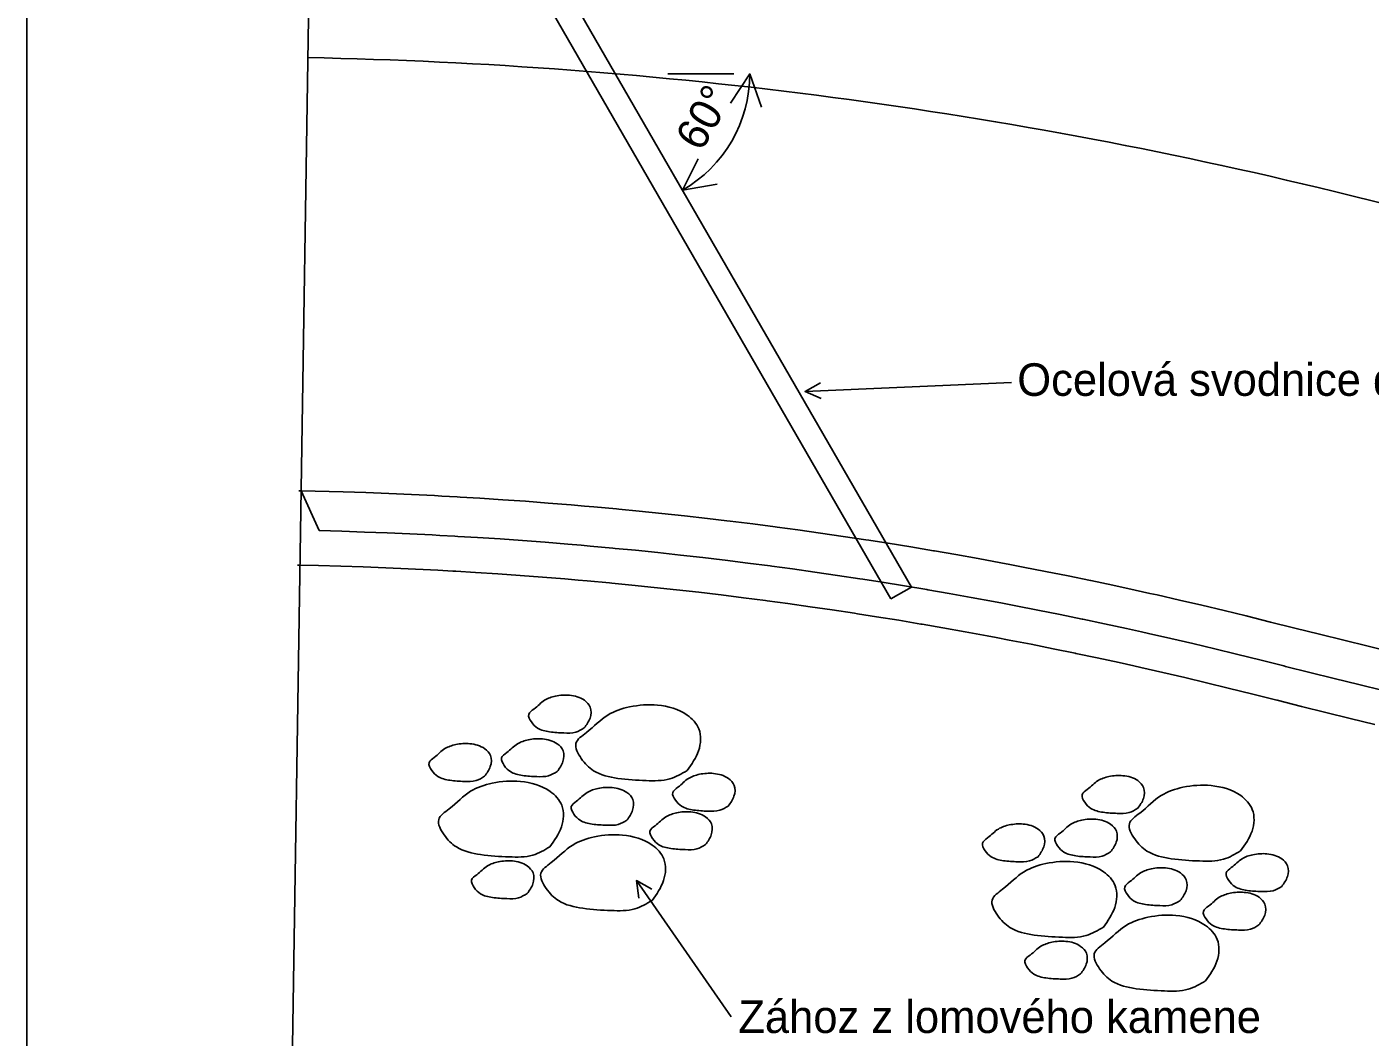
# Model space of a CAD drawing. Extents: x -577013.5 to -576971.5, y -1164310.3 to -1164280.6.
# Drawn here: x -577013.45 to -577004.93, y -1164296.24 to -1164289.83 of the extents above; entities that cross this region are included whole.
import ezdxf

# ---------------------------------------------------------------- set-up
doc = ezdxf.new("R2010")
doc.units = 0
for name, color, linetype in [('5', 7, 'Continuous'), ('Rámy', 7, 'Continuous'), ('V_N1_detaily', 7, 'Continuous'), ('Vrstva 1', 7, 'Continuous')]:
    doc.layers.add(name, color=color, linetype=linetype)

msp = doc.modelspace()

# ---------------------------------------------------------------- linework, layer by layer
for p, q in [((-577011.5826, -1164284.2581), (-577011.8184, -1164299.5379)), ((-577011.5089, -1164287.0275), (-577007.84, -1164293.3847)), ((-577007.9699, -1164293.4597), (-577011.6388, -1164287.1025)), ((-577009.3869, -1164290.1276), (-577008.9662, -1164290.128)), ((-577009.2943, -1164290.8648), (-577009.3432, -1164290.7801)), ((-577011.714, -1164292.7743), (-577011.7277, -1164292.7741)), ((-577011.4471, -1164292.7811), (-577011.714, -1164292.7737)), ((-577011.5982, -1164293.027), (-577011.714, -1164292.7743)), ((-577011.3022, -1164292.7859), (-577011.4471, -1164292.7811)), ((-577011.1574, -1164292.7914), (-577011.3022, -1164292.7859)), ((-577011.0127, -1164292.7977), (-577011.1574, -1164292.7914)), ((-577010.8679, -1164292.8048), (-577011.0127, -1164292.7977)), ((-577010.8202, -1164292.8073), (-577010.8679, -1164292.8048)), ((-577010.7232, -1164292.8126), (-577010.8202, -1164292.8073)), ((-577010.7043, -1164292.8137), (-577010.7232, -1164292.8126)), ((-577010.5786, -1164292.8212), (-577010.7043, -1164292.8137)), ((-577010.4339, -1164292.8306), (-577010.5786, -1164292.8212)), ((-577010.2894, -1164292.8408), (-577010.4339, -1164292.8306)), ((-577010.1449, -1164292.8517), (-577010.2894, -1164292.8408)), ((-577010.0004, -1164292.8634), (-577010.1449, -1164292.8517)), ((-577009.9141, -1164292.8707), (-577010.0004, -1164292.8634)), ((-577009.8561, -1164292.8758), (-577009.9141, -1164292.8707)), ((-577009.7117, -1164292.889), (-577009.8561, -1164292.8758)), ((-577009.6967, -1164292.8905), (-577009.7117, -1164292.889)), ((-577009.5675, -1164292.903), (-577009.6967, -1164292.8905)), ((-577009.4234, -1164292.9178), (-577009.5675, -1164292.903)), ((-577009.2793, -1164292.9333), (-577009.4234, -1164292.9178)), ((-577009.1353, -1164292.9496), (-577009.2793, -1164292.9333)), ((-577009.0106, -1164292.9643), (-577009.1353, -1164292.9496)), ((-577008.9914, -1164292.9667), (-577009.0106, -1164292.9643)), ((-577008.8476, -1164292.9845), (-577008.9914, -1164292.9667)), ((-577008.7038, -1164293.0031), (-577008.8476, -1164292.9845)), ((-577008.6927, -1164293.0045), (-577008.7038, -1164293.0031)), ((-577008.5602, -1164293.0224), (-577008.6927, -1164293.0045)), ((-577011.4546, -1164293.031), (-577011.5982, -1164293.027)), ((-577011.3111, -1164293.0357), (-577011.4546, -1164293.031)), ((-577011.1676, -1164293.0412), (-577011.3111, -1164293.0357)), ((-577011.0242, -1164293.0474), (-577011.1676, -1164293.0412)), ((-577010.8808, -1164293.0544), (-577011.0242, -1164293.0474)), ((-577010.8335, -1164293.0569), (-577010.8808, -1164293.0544)), ((-577010.7374, -1164293.0622), (-577010.8335, -1164293.0569)), ((-577010.7187, -1164293.0633), (-577010.7374, -1164293.0622)), ((-577010.5941, -1164293.0707), (-577010.7187, -1164293.0633)), ((-577010.4508, -1164293.08), (-577010.5941, -1164293.0707)), ((-577010.3076, -1164293.0901), (-577010.4508, -1164293.08)), ((-577010.1644, -1164293.1009), (-577010.3076, -1164293.0901)), ((-577008.4167, -1164293.0425), (-577008.5602, -1164293.0224)), ((-577008.2733, -1164293.0634), (-577008.4167, -1164293.0425)), ((-577008.13, -1164293.085), (-577008.2733, -1164293.0634)), ((-577008.1108, -1164293.088), (-577008.13, -1164293.085)), ((-577007.9868, -1164293.1074), (-577008.1108, -1164293.088)), ((-577010.0213, -1164293.1125), (-577010.1644, -1164293.1009)), ((-577009.9357, -1164293.1198), (-577010.0213, -1164293.1125)), ((-577009.8782, -1164293.1248), (-577009.9357, -1164293.1198)), ((-577009.7352, -1164293.1379), (-577009.8782, -1164293.1248)), ((-577009.7203, -1164293.1393), (-577009.7352, -1164293.1379)), ((-577009.5923, -1164293.1518), (-577009.7203, -1164293.1393)), ((-577009.4495, -1164293.1664), (-577009.5923, -1164293.1518)), ((-577009.3067, -1164293.1818), (-577009.4495, -1164293.1664)), ((-577009.164, -1164293.1979), (-577009.3067, -1164293.1818)), ((-577007.8438, -1164293.1306), (-577007.9868, -1164293.1074)), ((-577007.7009, -1164293.1545), (-577007.8438, -1164293.1306)), ((-577007.6935, -1164293.1558), (-577007.7009, -1164293.1545)), ((-577007.5581, -1164293.1792), (-577007.6935, -1164293.1558)), ((-577007.4154, -1164293.2046), (-577007.5581, -1164293.1792)), ((-577011.7236, -1164293.2461), (-577011.7373, -1164293.2458)), ((-577011.6037, -1164293.2488), (-577011.7236, -1164293.2461)), ((-577011.4613, -1164293.2527), (-577011.6037, -1164293.2488)), ((-577011.319, -1164293.2574), (-577011.4613, -1164293.2527)), ((-577011.1767, -1164293.2629), (-577011.319, -1164293.2574)), ((-577011.0344, -1164293.2691), (-577011.1767, -1164293.2629)), ((-577010.8922, -1164293.276), (-577011.0344, -1164293.2691)), ((-577009.0406, -1164293.2125), (-577009.164, -1164293.1979)), ((-577009.0214, -1164293.2148), (-577009.0406, -1164293.2125)), ((-577008.879, -1164293.2325), (-577009.0214, -1164293.2148)), ((-577008.7366, -1164293.2509), (-577008.879, -1164293.2325)), ((-577008.7255, -1164293.2524), (-577008.7366, -1164293.2509)), ((-577008.5943, -1164293.2701), (-577008.7255, -1164293.2524)), ((-577007.2729, -1164293.2308), (-577007.4154, -1164293.2046)), ((-577007.2156, -1164293.2416), (-577007.2729, -1164293.2308)), ((-577007.1305, -1164293.2578), (-577007.2156, -1164293.2416)), ((-577006.9882, -1164293.2855), (-577007.1305, -1164293.2578)), ((-577010.8453, -1164293.2785), (-577010.8922, -1164293.276)), ((-577010.75, -1164293.2837), (-577010.8453, -1164293.2785)), ((-577010.7314, -1164293.2848), (-577010.75, -1164293.2837)), ((-577010.6078, -1164293.2922), (-577010.7314, -1164293.2848)), ((-577010.4657, -1164293.3014), (-577010.6078, -1164293.2922)), ((-577010.3237, -1164293.3114), (-577010.4657, -1164293.3014)), ((-577010.1817, -1164293.3221), (-577010.3237, -1164293.3114)), ((-577010.0397, -1164293.3336), (-577010.1817, -1164293.3221)), ((-577009.9549, -1164293.3408), (-577010.0397, -1164293.3336)), ((-577009.8979, -1164293.3458), (-577009.9549, -1164293.3408)), ((-577009.7561, -1164293.3588), (-577009.8979, -1164293.3458)), ((-577008.4521, -1164293.29), (-577008.5943, -1164293.2701)), ((-577008.31, -1164293.3107), (-577008.4521, -1164293.29)), ((-577008.168, -1164293.3321), (-577008.31, -1164293.3107)), ((-577008.149, -1164293.3351), (-577008.168, -1164293.3321)), ((-577008.0261, -1164293.3543), (-577008.149, -1164293.3351)), ((-577007.8844, -1164293.3773), (-577008.0261, -1164293.3543)), ((-577006.8461, -1164293.314), (-577006.9882, -1164293.2855)), ((-577006.7042, -1164293.3432), (-577006.8461, -1164293.314)), ((-577006.7007, -1164293.3439), (-577006.7042, -1164293.3432)), ((-577006.5624, -1164293.3732), (-577006.7007, -1164293.3439)), ((-577009.7413, -1164293.3602), (-577009.7561, -1164293.3588)), ((-577009.6143, -1164293.3726), (-577009.7413, -1164293.3602)), ((-577009.4726, -1164293.3871), (-577009.6143, -1164293.3726)), ((-577009.3311, -1164293.4023), (-577009.4726, -1164293.3871)), ((-577009.1896, -1164293.4183), (-577009.3311, -1164293.4023)), ((-577009.0671, -1164293.4328), (-577009.1896, -1164293.4183)), ((-577009.0481, -1164293.4351), (-577009.0671, -1164293.4328)), ((-577008.9068, -1164293.4526), (-577009.0481, -1164293.4351)), ((-577007.84, -1164293.3847), (-577007.9699, -1164293.4597)), ((-577007.7428, -1164293.401), (-577007.8844, -1164293.3773)), ((-577007.7355, -1164293.4022), (-577007.7428, -1164293.401)), ((-577007.6013, -1164293.4254), (-577007.7355, -1164293.4022)), ((-577007.4599, -1164293.4506), (-577007.6013, -1164293.4254)), ((-577006.4208, -1164293.4039), (-577006.5624, -1164293.3732)), ((-577006.326, -1164293.4249), (-577006.4208, -1164293.4039)), ((-577006.2794, -1164293.4354), (-577006.326, -1164293.4249)), ((-577006.1381, -1164293.4676), (-577006.2794, -1164293.4354)), ((-577008.7656, -1164293.4709), (-577008.9068, -1164293.4526)), ((-577008.7546, -1164293.4723), (-577008.7656, -1164293.4709)), ((-577008.6245, -1164293.4899), (-577008.7546, -1164293.4723)), ((-577008.4834, -1164293.5096), (-577008.6245, -1164293.4899)), ((-577008.3425, -1164293.5302), (-577008.4834, -1164293.5096)), ((-577007.3187, -1164293.4766), (-577007.4599, -1164293.4506)), ((-577007.262, -1164293.4872), (-577007.3187, -1164293.4766)), ((-577007.1776, -1164293.5033), (-577007.262, -1164293.4872)), ((-577007.0367, -1164293.5307), (-577007.1776, -1164293.5033)), ((-577005.997, -1164293.5006), (-577006.1381, -1164293.4676)), ((-577005.856, -1164293.5343), (-577005.997, -1164293.5006)), ((-577008.2017, -1164293.5514), (-577008.3425, -1164293.5302)), ((-577008.1828, -1164293.5543), (-577008.2017, -1164293.5514)), ((-577008.061, -1164293.5734), (-577008.1828, -1164293.5543)), ((-577007.9204, -1164293.5962), (-577008.061, -1164293.5734)), ((-577007.78, -1164293.6197), (-577007.9204, -1164293.5962)), ((-577006.8959, -1164293.559), (-577007.0367, -1164293.5307)), ((-577006.7553, -1164293.5879), (-577006.8959, -1164293.559)), ((-577006.7518, -1164293.5886), (-577006.7553, -1164293.5879)), ((-577006.6148, -1164293.6176), (-577006.7518, -1164293.5886)), ((-577005.7156, -1164293.5687), (-577005.856, -1164293.5343)), ((-577005.5604, -1164293.6072), (-577005.7156, -1164293.5687)), ((-577005.4151, -1164293.6432), (-577005.5604, -1164293.6072)), ((-577007.7728, -1164293.6209), (-577007.78, -1164293.6197)), ((-577007.6397, -1164293.6439), (-577007.7728, -1164293.6209)), ((-577007.4995, -1164293.6689), (-577007.6397, -1164293.6439)), ((-577007.3594, -1164293.6947), (-577007.4995, -1164293.6689)), ((-577007.3031, -1164293.7052), (-577007.3594, -1164293.6947)), ((-577006.4745, -1164293.6481), (-577006.6148, -1164293.6176)), ((-577006.3805, -1164293.6689), (-577006.4745, -1164293.6481)), ((-577006.3343, -1164293.6793), (-577006.3805, -1164293.6689)), ((-577006.1943, -1164293.7112), (-577006.3343, -1164293.6793)), ((-577005.4055, -1164293.6456), (-577005.4151, -1164293.6432)), ((-577005.2507, -1164293.684), (-577005.4055, -1164293.6456)), ((-577005.0958, -1164293.7223), (-577005.2507, -1164293.684)), ((-577007.2195, -1164293.7212), (-577007.3031, -1164293.7052)), ((-577007.0797, -1164293.7484), (-577007.2195, -1164293.7212)), ((-577006.9401, -1164293.7764), (-577007.0797, -1164293.7484)), ((-577006.8006, -1164293.8051), (-577006.9401, -1164293.7764)), ((-577006.0545, -1164293.7439), (-577006.1943, -1164293.7112)), ((-577005.9149, -1164293.7773), (-577006.0545, -1164293.7439)), ((-577005.7757, -1164293.8114), (-577005.9149, -1164293.7773)), ((-577004.941, -1164293.7607), (-577005.0958, -1164293.7223)), ((-577004.7861, -1164293.7991), (-577004.941, -1164293.7607)), ((-577006.7972, -1164293.8058), (-577006.8006, -1164293.8051)), ((-577006.6613, -1164293.8346), (-577006.7972, -1164293.8058)), ((-577006.5221, -1164293.8648), (-577006.6613, -1164293.8346)), ((-577006.4289, -1164293.8854), (-577006.5221, -1164293.8648)), ((-577005.6205, -1164293.8499), (-577005.7757, -1164293.8114)), ((-577005.4753, -1164293.8859), (-577005.6205, -1164293.8499)), ((-577006.3831, -1164293.8957), (-577006.4289, -1164293.8854)), ((-577006.2443, -1164293.9274), (-577006.3831, -1164293.8957)), ((-577006.1056, -1164293.9598), (-577006.2443, -1164293.9274)), ((-577005.4657, -1164293.8882), (-577005.4753, -1164293.8859)), ((-577005.3108, -1164293.9266), (-577005.4657, -1164293.8882)), ((-577005.156, -1164293.965), (-577005.3108, -1164293.9266)), ((-577005.9671, -1164293.9929), (-577006.1056, -1164293.9598)), ((-577005.8291, -1164294.0268), (-577005.9671, -1164293.9929)), ((-577005.6739, -1164294.0652), (-577005.8291, -1164294.0268)), ((-577005.0011, -1164294.0034), (-577005.156, -1164293.965)), ((-577004.8463, -1164294.0417), (-577005.0011, -1164294.0034)), ((-577005.5286, -1164294.1012), (-577005.6739, -1164294.0652)), ((-577005.519, -1164294.1036), (-577005.5286, -1164294.1012)), ((-577005.3642, -1164294.142), (-577005.519, -1164294.1036)), ((-577005.2093, -1164294.1803), (-577005.3642, -1164294.142)), ((-577005.0545, -1164294.2187), (-577005.2093, -1164294.1803)), ((-577004.8996, -1164294.2571), (-577005.0545, -1164294.2187))]:
    msp.add_line(p, q)
for points in [[(-577008.9891, -1164290.3149), (-577008.8662, -1164290.1281), (-577008.7905, -1164290.3385)], [(-577009.0731, -1164290.8273), (-577009.2932, -1164290.8667), (-577009.1927, -1164290.667)]]:
    msp.add_lwpolyline(points)
msp.add_arc((-577009.72, -1164290.1273), 0.8538, 299.99035, 359.94545)
at = {"layer": '5'}
msp.add_line((-576992.1353, -1164294.101), (-577005.0541, -1164290.8995), dxfattribs=at)
msp.add_arc((-577012.2703, -1164320.0187), 30, 76.08153, 88.85648, dxfattribs=at)
at = {"layer": 'Rámy'}
msp.add_line((-577013.4543, -1164310.2564), (-577013.4543, -1164280.5564), dxfattribs=at)
at = {"layer": 'V_N1_detaily'}
for points in [[(-577009.9161, -1164294.2789), (-577009.9708, -1164294.3058), (-577010.0461, -1164294.3111), (-577010.1362, -1164294.3041), (-577010.2133, -1164294.2797), (-577010.2523, -1164294.241), (-577010.2692, -1164294.193), (-577010.2361, -1164294.159), (-577010.168, -1164294.1032), (-577010.0991, -1164294.0774), (-577010.01, -1164294.0719), (-577009.9159, -1164294.1035), (-577009.8791, -1164294.1475), (-577009.88, -1164294.2162), (-577009.9161, -1164294.2789)], [(-577009.2632, -1164294.5488), (-577009.3726, -1164294.6024), (-577009.5231, -1164294.6132), (-577009.7033, -1164294.5991), (-577009.8575, -1164294.5504), (-577009.9355, -1164294.4728), (-577009.9694, -1164294.377), (-577009.9032, -1164294.3089), (-577009.767, -1164294.1973), (-577009.6292, -1164294.1456), (-577009.4509, -1164294.1347), (-577009.2627, -1164294.1979), (-577009.189, -1164294.2858), (-577009.1909, -1164294.4234), (-577009.2632, -1164294.5488)], [(-577010.5488, -1164294.5862), (-577010.6035, -1164294.613), (-577010.6788, -1164294.6184), (-577010.7689, -1164294.6113), (-577010.846, -1164294.587), (-577010.885, -1164294.5482), (-577010.9019, -1164294.5003), (-577010.8688, -1164294.4663), (-577010.8007, -1164294.4105), (-577010.7318, -1164294.3846), (-577010.6427, -1164294.3792), (-577010.5486, -1164294.4108), (-577010.5117, -1164294.4547), (-577010.5127, -1164294.5235), (-577010.5488, -1164294.5862)], [(-577010.0883, -1164294.5557), (-577010.143, -1164294.5825), (-577010.2182, -1164294.5879), (-577010.3083, -1164294.5809), (-577010.3854, -1164294.5565), (-577010.4244, -1164294.5177), (-577010.4414, -1164294.4698), (-577010.4083, -1164294.4358), (-577010.3402, -1164294.38), (-577010.2713, -1164294.3542), (-577010.1821, -1164294.3487), (-577010.088, -1164294.3803), (-577010.0512, -1164294.4242), (-577010.0521, -1164294.493), (-577010.0883, -1164294.5557)], [(-577010.1341, -1164295.0329), (-577010.2434, -1164295.0865), (-577010.394, -1164295.0973), (-577010.5741, -1164295.0831), (-577010.7283, -1164295.0344), (-577010.8063, -1164294.9569), (-577010.8402, -1164294.8611), (-577010.7741, -1164294.793), (-577010.6378, -1164294.6813), (-577010.5001, -1164294.6297), (-577010.3217, -1164294.6188), (-577010.1336, -1164294.682), (-577010.0599, -1164294.7699), (-577010.0617, -1164294.9074), (-577010.1341, -1164295.0329)], [(-577009.0023, -1164294.775), (-577009.0569, -1164294.8018), (-577009.1322, -1164294.8072), (-577009.2223, -1164294.8002), (-577009.2994, -1164294.7758), (-577009.3384, -1164294.737), (-577009.3553, -1164294.6891), (-577009.3223, -1164294.6551), (-577009.2541, -1164294.5993), (-577009.1853, -1164294.5734), (-577009.0961, -1164294.568), (-577009.002, -1164294.5996), (-577008.9652, -1164294.6435), (-577008.9661, -1164294.7123), (-577009.0023, -1164294.775)], [(-577006.4035, -1164294.7891), (-577006.4582, -1164294.8159), (-577006.5334, -1164294.8213), (-577006.6235, -1164294.8143), (-577006.7006, -1164294.7899), (-577006.7396, -1164294.7512), (-577006.7566, -1164294.7032), (-577006.7235, -1164294.6692), (-577006.6554, -1164294.6134), (-577006.5865, -1164294.5876), (-577006.4973, -1164294.5821), (-577006.4032, -1164294.6137), (-577006.3664, -1164294.6577), (-577006.3673, -1164294.7264), (-577006.4035, -1164294.7891)], [(-577009.6459, -1164294.8644), (-577009.7006, -1164294.8912), (-577009.7759, -1164294.8966), (-577009.866, -1164294.8895), (-577009.9431, -1164294.8652), (-577009.9821, -1164294.8264), (-577009.999, -1164294.7785), (-577009.9659, -1164294.7444), (-577009.8978, -1164294.6886), (-577009.8289, -1164294.6628), (-577009.7398, -1164294.6573), (-577009.6457, -1164294.6889), (-577009.6089, -1164294.7329), (-577009.6098, -1164294.8017), (-577009.6459, -1164294.8644)], [(-577005.7506, -1164295.059), (-577005.8599, -1164295.1126), (-577006.0105, -1164295.1234), (-577006.1907, -1164295.1093), (-577006.3449, -1164295.0606), (-577006.4228, -1164294.983), (-577006.4567, -1164294.8872), (-577006.3906, -1164294.8191), (-577006.2543, -1164294.7075), (-577006.1166, -1164294.6558), (-577005.9382, -1164294.6449), (-577005.7501, -1164294.7081), (-577005.6764, -1164294.796), (-577005.6783, -1164294.9336), (-577005.7506, -1164295.059)], [(-577009.1466, -1164295.0194), (-577009.2012, -1164295.0462), (-577009.2765, -1164295.0516), (-577009.3666, -1164295.0445), (-577009.4437, -1164295.0202), (-577009.4827, -1164294.9814), (-577009.4996, -1164294.9335), (-577009.4666, -1164294.8994), (-577009.3984, -1164294.8436), (-577009.3296, -1164294.8178), (-577009.2404, -1164294.8123), (-577009.1463, -1164294.8439), (-577009.1095, -1164294.8879), (-577009.1104, -1164294.9566), (-577009.1466, -1164295.0194)], [(-577007.0362, -1164295.0964), (-577007.0909, -1164295.1232), (-577007.1661, -1164295.1286), (-577007.2562, -1164295.1215), (-577007.3333, -1164295.0972), (-577007.3723, -1164295.0584), (-577007.3893, -1164295.0105), (-577007.3562, -1164294.9765), (-577007.2881, -1164294.9206), (-577007.2192, -1164294.8948), (-577007.13, -1164294.8894), (-577007.0359, -1164294.921), (-577006.9991, -1164294.9649), (-577007, -1164295.0337), (-577007.0362, -1164295.0964)], [(-577006.5756, -1164295.0659), (-577006.6303, -1164295.0927), (-577006.7056, -1164295.0981), (-577006.7957, -1164295.0911), (-577006.8728, -1164295.0667), (-577006.9118, -1164295.0279), (-577006.9287, -1164294.98), (-577006.8956, -1164294.946), (-577006.8275, -1164294.8902), (-577006.7586, -1164294.8643), (-577006.6694, -1164294.8589), (-577006.5754, -1164294.8905), (-577006.5385, -1164294.9344), (-577006.5395, -1164295.0032), (-577006.5756, -1164295.0659)], [(-577009.4858, -1164295.3736), (-577009.5951, -1164295.4272), (-577009.7457, -1164295.438), (-577009.9258, -1164295.4239), (-577010.08, -1164295.3752), (-577010.158, -1164295.2976), (-577010.1919, -1164295.2018), (-577010.1258, -1164295.1337), (-577009.9895, -1164295.0221), (-577009.8518, -1164294.9704), (-577009.6734, -1164294.9595), (-577009.4853, -1164295.0227), (-577009.4116, -1164295.1106), (-577009.4134, -1164295.2482), (-577009.4858, -1164295.3736)], [(-577010.2787, -1164295.3303), (-577010.3334, -1164295.3571), (-577010.4087, -1164295.3625), (-577010.4988, -1164295.3555), (-577010.5759, -1164295.3311), (-577010.6149, -1164295.2924), (-577010.6318, -1164295.2444), (-577010.5987, -1164295.2104), (-577010.5306, -1164295.1546), (-577010.4617, -1164295.1288), (-577010.3726, -1164295.1233), (-577010.2785, -1164295.1549), (-577010.2416, -1164295.1989), (-577010.2426, -1164295.2676), (-577010.2787, -1164295.3303)], [(-577006.6214, -1164295.543), (-577006.7308, -1164295.5967), (-577006.8813, -1164295.6075), (-577007.0615, -1164295.5933), (-577007.2157, -1164295.5446), (-577007.2937, -1164295.4671), (-577007.3276, -1164295.3713), (-577007.2614, -1164295.3032), (-577007.1252, -1164295.1915), (-577006.9874, -1164295.1399), (-577006.809, -1164295.1289), (-577006.6209, -1164295.1921), (-577006.5472, -1164295.2801), (-577006.5491, -1164295.4176), (-577006.6214, -1164295.543)], [(-577005.4896, -1164295.2852), (-577005.5443, -1164295.312), (-577005.6196, -1164295.3174), (-577005.7096, -1164295.3103), (-577005.7867, -1164295.286), (-577005.8257, -1164295.2472), (-577005.8427, -1164295.1993), (-577005.8096, -1164295.1653), (-577005.7415, -1164295.1095), (-577005.6726, -1164295.0836), (-577005.5834, -1164295.0782), (-577005.4894, -1164295.1098), (-577005.4525, -1164295.1537), (-577005.4534, -1164295.2225), (-577005.4896, -1164295.2852)], [(-577006.1333, -1164295.3746), (-577006.188, -1164295.4014), (-577006.2632, -1164295.4068), (-577006.3533, -1164295.3997), (-577006.4304, -1164295.3754), (-577006.4694, -1164295.3366), (-577006.4864, -1164295.2887), (-577006.4533, -1164295.2546), (-577006.3852, -1164295.1988), (-577006.3163, -1164295.173), (-577006.2271, -1164295.1675), (-577006.133, -1164295.1991), (-577006.0962, -1164295.2431), (-577006.0971, -1164295.3119), (-577006.1333, -1164295.3746)], [(-577005.6339, -1164295.5296), (-577005.6886, -1164295.5564), (-577005.7639, -1164295.5618), (-577005.8539, -1164295.5547), (-577005.931, -1164295.5303), (-577005.97, -1164295.4916), (-577005.987, -1164295.4437), (-577005.9539, -1164295.4096), (-577005.8858, -1164295.3538), (-577005.8169, -1164295.328), (-577005.7277, -1164295.3225), (-577005.6337, -1164295.3541), (-577005.5968, -1164295.3981), (-577005.5977, -1164295.4668), (-577005.6339, -1164295.5296)], [(-577005.9731, -1164295.8838), (-577006.0825, -1164295.9374), (-577006.233, -1164295.9482), (-577006.4132, -1164295.9341), (-577006.5674, -1164295.8854), (-577006.6454, -1164295.8078), (-577006.6793, -1164295.712), (-577006.6131, -1164295.6439), (-577006.4769, -1164295.5323), (-577006.3391, -1164295.4806), (-577006.1607, -1164295.4697), (-577005.9726, -1164295.5329), (-577005.8989, -1164295.6208), (-577005.9008, -1164295.7584), (-577005.9731, -1164295.8838)], [(-577006.7661, -1164295.8405), (-577006.8208, -1164295.8673), (-577006.896, -1164295.8727), (-577006.9861, -1164295.8657), (-577007.0632, -1164295.8413), (-577007.1022, -1164295.8025), (-577007.1192, -1164295.7546), (-577007.0861, -1164295.7206), (-577007.018, -1164295.6648), (-577006.9491, -1164295.639), (-577006.8599, -1164295.6335), (-577006.7658, -1164295.6651), (-577006.729, -1164295.709), (-577006.7299, -1164295.7778), (-577006.7661, -1164295.8405)]]:
    msp.add_spline(points, degree=3, dxfattribs=at)
at = {"layer": 'Vrstva 1'}
for p, q in [((-577008.5144, -1164292.1437), (-577007.2045, -1164292.0869)), ((-577009.5853, -1164295.2479), (-577008.9835, -1164296.1117))]:
    msp.add_line(p, q, dxfattribs=at)
for points in [[(-577008.4124, -1164292.1893), (-577008.5144, -1164292.1437), (-577008.4167, -1164292.0894)], [(-577009.5692, -1164295.3585), (-577009.5853, -1164295.2479), (-577009.4871, -1164295.3013)]]:
    msp.add_lwpolyline(points, dxfattribs=at)

# ---------------------------------------------------------------- texts
msp.add_text('60°', height=0.2, rotation=59.9679).set_placement((-577009.1743, -1164290.6284))
for s, p in [('Ocelová svodnice dl. 7,5m', (-577007.1681, -1164292.1716)), ('Zához z lomového kamene ', (-577008.9388, -1164296.215))]:
    msp.add_text(s, height=0.206627, dxfattribs=at).set_placement(p)

doc.saveas('drawing.dxf')
